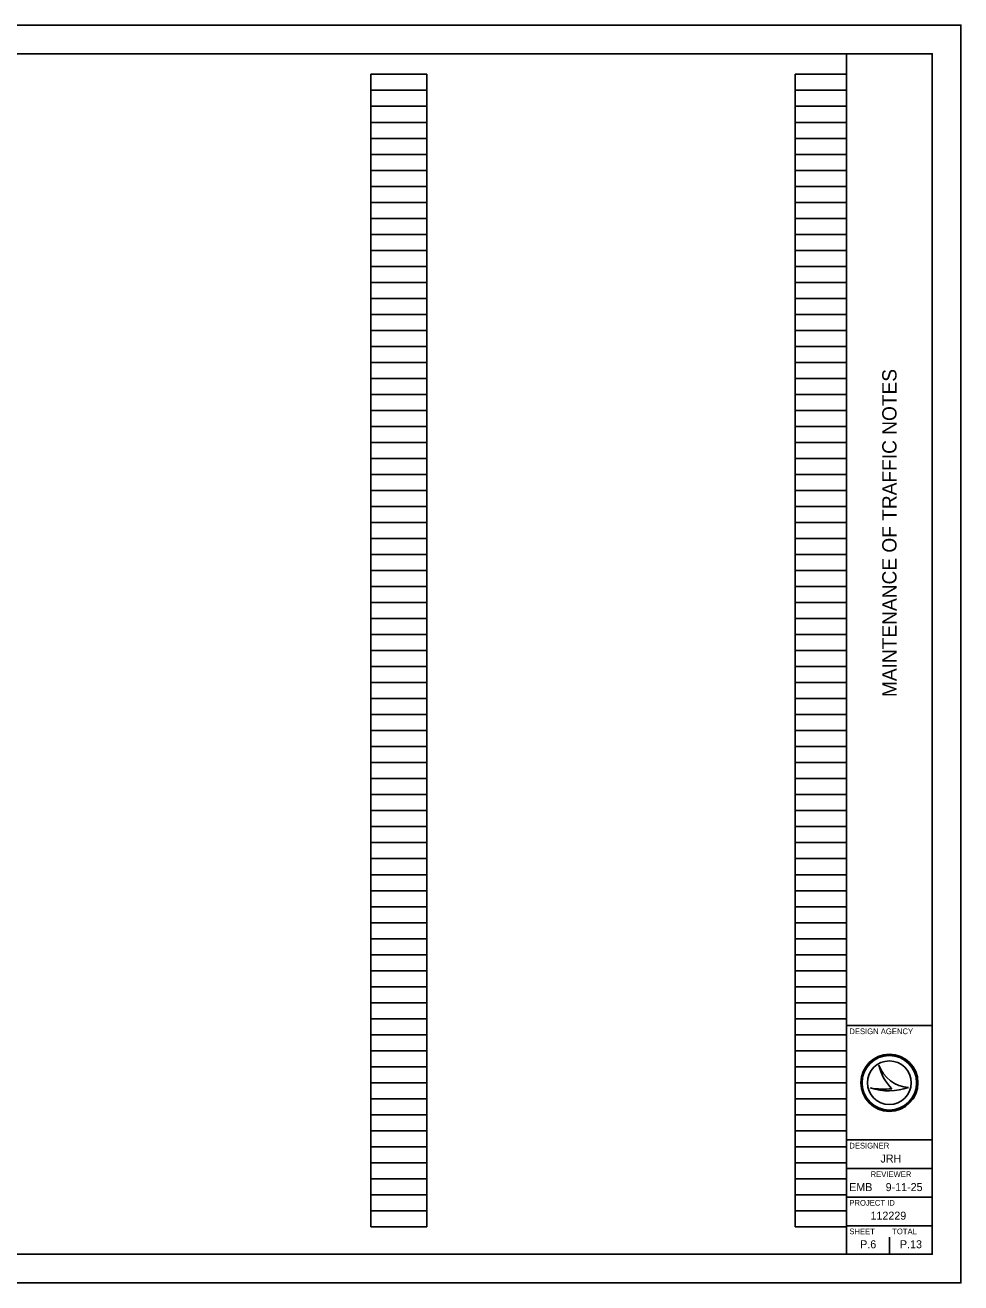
# Model space of a CAD drawing. Extents: x 0 to 34, y 0 to 22.
# Drawn here: x 17.63 to 34, y 0 to 22 of the extents above; entities that cross this region are included whole.
import ezdxf

# ---------------------------------------------------------------- set-up
doc = ezdxf.new("R2010")
doc.units = 0
for name, color, linetype in [('SH_Border', 7, 'Continuous'), ('SH_Cut_Line', 7, 'Continuous'), ('SH_Data', 7, 'Continuous')]:
    doc.layers.add(name, color=color, linetype=linetype)

msp = doc.modelspace()

# ---------------------------------------------------------------- linework, layer by layer
at = {"layer": 'SH_Border'}
for p, q in [((32, 0.5), (32, 21.5)), ((32, 4.5), (33.5, 4.5)), ((32, 2.5), (33.5, 2.5)), ((32, 2), (33.5, 2)), ((32, 1.5), (33.5, 1.5)), ((32, 1), (33.5, 1))]:
    msp.add_line(p, q, dxfattribs=at)
msp.add_lwpolyline([(1.5, 21.5), (33.5, 21.5), (33.5, 0.5), (1.5, 0.5)], close=True, dxfattribs=at)
at = {"layer": 'SH_Cut_Line'}
msp.add_lwpolyline([(0, 0), (34, 0), (34, 22), (0, 22)], close=True, dxfattribs=at)
at = {"layer": 'SH_Data'}
for p, q in [((23.68, 0.98), (23.68, 21.14)), ((23.68, 21.14), (24.66, 21.14)), ((24.66, 0.98), (24.66, 21.14)), ((31.1, 0.98), (31.1, 21.14)), ((31.1, 21.14), (32, 21.14)), ((32, 0.98), (32, 21.14)), ((23.68, 20.86), (24.66, 20.86)), ((31.1, 20.86), (32, 20.86)), ((23.68, 20.58), (24.66, 20.58)), ((31.1, 20.58), (32, 20.58)), ((23.68, 20.3), (24.66, 20.3)), ((31.1, 20.3), (32, 20.3)), ((23.68, 20.02), (24.66, 20.02)), ((31.1, 20.02), (32, 20.02)), ((23.68, 19.74), (24.66, 19.74)), ((31.1, 19.74), (32, 19.74)), ((23.68, 19.46), (24.66, 19.46)), ((31.1, 19.46), (32, 19.46)), ((23.68, 19.18), (24.66, 19.18)), ((31.1, 19.18), (32, 19.18)), ((23.68, 18.9), (24.66, 18.9)), ((31.1, 18.9), (32, 18.9)), ((23.68, 18.62), (24.66, 18.62)), ((31.1, 18.62), (32, 18.62)), ((23.68, 18.34), (24.66, 18.34)), ((31.1, 18.34), (32, 18.34)), ((23.68, 18.06), (24.66, 18.06)), ((31.1, 18.06), (32, 18.06)), ((23.68, 17.78), (24.66, 17.78)), ((31.1, 17.78), (32, 17.78)), ((23.68, 17.5), (24.66, 17.5)), ((31.1, 17.5), (32, 17.5)), ((23.68, 17.22), (24.66, 17.22)), ((31.1, 17.22), (32, 17.22)), ((23.68, 16.94), (24.66, 16.94)), ((31.1, 16.94), (32, 16.94)), ((23.68, 16.66), (24.66, 16.66)), ((31.1, 16.66), (32, 16.66)), ((23.68, 16.38), (24.66, 16.38)), ((31.1, 16.38), (32, 16.38)), ((23.68, 16.1), (24.66, 16.1)), ((31.1, 16.1), (32, 16.1)), ((23.68, 15.82), (24.66, 15.82)), ((31.1, 15.82), (32, 15.82)), ((23.68, 15.54), (24.66, 15.54)), ((31.1, 15.54), (32, 15.54)), ((23.68, 15.26), (24.66, 15.26)), ((31.1, 15.26), (32, 15.26)), ((23.68, 14.98), (24.66, 14.98)), ((31.1, 14.98), (32, 14.98)), ((23.68, 14.7), (24.66, 14.7)), ((31.1, 14.7), (32, 14.7)), ((23.68, 14.42), (24.66, 14.42)), ((31.1, 14.42), (32, 14.42)), ((23.68, 14.14), (24.66, 14.14)), ((31.1, 14.14), (32, 14.14)), ((23.68, 13.86), (24.66, 13.86)), ((31.1, 13.86), (32, 13.86)), ((23.68, 13.58), (24.66, 13.58)), ((31.1, 13.58), (32, 13.58)), ((23.68, 13.3), (24.66, 13.3)), ((31.1, 13.3), (32, 13.3)), ((23.68, 13.02), (24.66, 13.02)), ((31.1, 13.02), (32, 13.02)), ((23.68, 12.74), (24.66, 12.74)), ((31.1, 12.74), (32, 12.74)), ((23.68, 12.46), (24.66, 12.46)), ((31.1, 12.46), (32, 12.46)), ((23.68, 12.18), (24.66, 12.18)), ((31.1, 12.18), (32, 12.18)), ((23.68, 11.9), (24.66, 11.9)), ((31.1, 11.9), (32, 11.9)), ((23.68, 11.62), (24.66, 11.62)), ((31.1, 11.62), (32, 11.62)), ((23.68, 11.34), (24.66, 11.34)), ((31.1, 11.34), (32, 11.34)), ((23.68, 11.06), (24.66, 11.06)), ((31.1, 11.06), (32, 11.06)), ((23.68, 10.78), (24.66, 10.78)), ((31.1, 10.78), (32, 10.78)), ((23.68, 10.5), (24.66, 10.5)), ((31.1, 10.5), (32, 10.5)), ((23.68, 10.22), (24.66, 10.22)), ((31.1, 10.22), (32, 10.22)), ((23.68, 9.94), (24.66, 9.94)), ((31.1, 9.94), (32, 9.94)), ((23.68, 9.66), (24.66, 9.66)), ((31.1, 9.66), (32, 9.66)), ((23.68, 9.38), (24.66, 9.38)), ((31.1, 9.38), (32, 9.38)), ((23.68, 9.1), (24.66, 9.1)), ((31.1, 9.1), (32, 9.1)), ((23.68, 8.82), (24.66, 8.82)), ((31.1, 8.82), (32, 8.82)), ((23.68, 8.54), (24.66, 8.54)), ((31.1, 8.54), (32, 8.54)), ((23.68, 8.26), (24.66, 8.26)), ((31.1, 8.26), (32, 8.26)), ((23.68, 7.98), (24.66, 7.98)), ((31.1, 7.98), (32, 7.98)), ((23.68, 7.7), (24.66, 7.7)), ((31.1, 7.7), (32, 7.7)), ((23.68, 7.42), (24.66, 7.42)), ((31.1, 7.42), (32, 7.42)), ((23.68, 7.14), (24.66, 7.14)), ((31.1, 7.14), (32, 7.14)), ((23.68, 6.86), (24.66, 6.86)), ((31.1, 6.86), (32, 6.86)), ((23.68, 6.58), (24.66, 6.58)), ((31.1, 6.58), (32, 6.58)), ((23.68, 6.3), (24.66, 6.3)), ((31.1, 6.3), (32, 6.3)), ((23.68, 6.02), (24.66, 6.02)), ((31.1, 6.02), (32, 6.02)), ((23.68, 5.74), (24.66, 5.74)), ((31.1, 5.74), (32, 5.74)), ((23.68, 5.46), (24.66, 5.46)), ((31.1, 5.46), (32, 5.46)), ((23.68, 5.18), (24.66, 5.18)), ((31.1, 5.18), (32, 5.18)), ((23.68, 4.9), (24.66, 4.9)), ((31.1, 4.9), (32, 4.9)), ((23.68, 4.62), (24.66, 4.62)), ((31.1, 4.62), (32, 4.62)), ((23.68, 4.34), (24.66, 4.34)), ((31.1, 4.34), (32, 4.34)), ((23.68, 4.06), (24.66, 4.06)), ((31.1, 4.06), (32, 4.06)), ((23.68, 3.78), (24.66, 3.78)), ((31.1, 3.78), (32, 3.78)), ((32.567, 3.81), (32.567, 3.81)), ((23.68, 3.5), (24.66, 3.5)), ((31.1, 3.5), (32, 3.5)), ((32.417, 3.41), (32.417, 3.41)), ((32.75, 3.5), (32.75, 3.5)), ((33.087, 3.419), (33.087, 3.419)), ((23.68, 3.22), (24.66, 3.22)), ((31.1, 3.22), (32, 3.22)), ((23.68, 2.94), (24.66, 2.94)), ((31.1, 2.94), (32, 2.94)), ((23.68, 2.66), (24.66, 2.66)), ((31.1, 2.66), (32, 2.66)), ((23.68, 2.38), (24.66, 2.38)), ((31.1, 2.38), (32, 2.38)), ((23.68, 2.1), (24.66, 2.1)), ((31.1, 2.1), (32, 2.1)), ((23.68, 1.82), (24.66, 1.82)), ((31.1, 1.82), (32, 1.82)), ((23.68, 1.54), (24.66, 1.54)), ((31.1, 1.54), (32, 1.54)), ((23.68, 1.26), (24.66, 1.26)), ((31.1, 1.26), (32, 1.26)), ((23.68, 0.98), (24.66, 0.98)), ((31.1, 0.98), (32, 0.98)), ((32.375, 0.675), (32.375, 0.675)), ((32.75, 0.5), (32.75, 0.8))]:
    msp.add_line(p, q, dxfattribs=at)
for radius in [0.5, 0.477, 0.477, 0.382]:
    msp.add_circle((32.75, 3.5), radius, dxfattribs=at)
for centre, radius, start, end in [((33.116, 3.998), 0.58, 198.9257, 198.9319), ((33.347, 3.97), 0.796, 191.6379, 191.6421), ((33.116, 3.998), 0.58, 198.9319, 267.1657), ((33.347, 3.97), 0.796, 191.6421, 226.0947), ((32.739, 4.37), 1.013, 251.4576, 290.0832), ((32.648, 4.654), 1.266, 259.4964, 259.4995), ((32.739, 4.37), 1.013, 251.4527, 251.4576), ((32.648, 4.654), 1.266, 259.4995, 276.6672)]:
    msp.add_arc(centre, radius, start, end, dxfattribs=at)

# ---------------------------------------------------------------- texts
msp.add_text('MAINTENANCE OF TRAFFIC NOTES', height=0.25, rotation=90, dxfattribs=at).set_placement((32.875, 10.247))
for s, height, p in [('DESIGN AGENCY', 0.1, (32.05, 4.35)), ('DESIGNER', 0.1, (32.05, 2.35)), ('JRH', 0.14, (32.595, 2.105)), ('REVIEWER', 0.1, (32.422, 1.85)), ('EMB', 0.14, (32.047, 1.605)), ('9-11-25', 0.14, (32.685, 1.605)), ('PROJECT ID', 0.1, (32.05, 1.35)), ('112229', 0.14, (32.42, 1.105)), ('SHEET', 0.1, (32.05, 0.85)), ('TOTAL', 0.1, (32.8, 0.85)), ('P.6', 0.14, (32.239, 0.605)), ('P.13', 0.14, (32.935, 0.605))]:
    msp.add_text(s, height=height, dxfattribs=at).set_placement(p)

doc.saveas('drawing.dxf')
